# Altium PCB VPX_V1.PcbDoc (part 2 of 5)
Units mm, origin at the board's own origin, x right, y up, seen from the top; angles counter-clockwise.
Board outline 157.76 x 100.08 mm, 10 copper layers (Top Layer (PADS/SIG), Layer 2 (GND), Layer 3 (SIG), Layer 4 (SIG), Layer 5 (GND), Layer 6 (PWR), Layer 7 (GND), Layer 8 (SIG/PWR), Layer 9 (GND), Bottom Layer (PAD/SIG)), stack 1.614 mm thick; 383 components, 223 nets, 1313 pads, 1223 vias.
Unrouted connection lines stored in the file: 3.
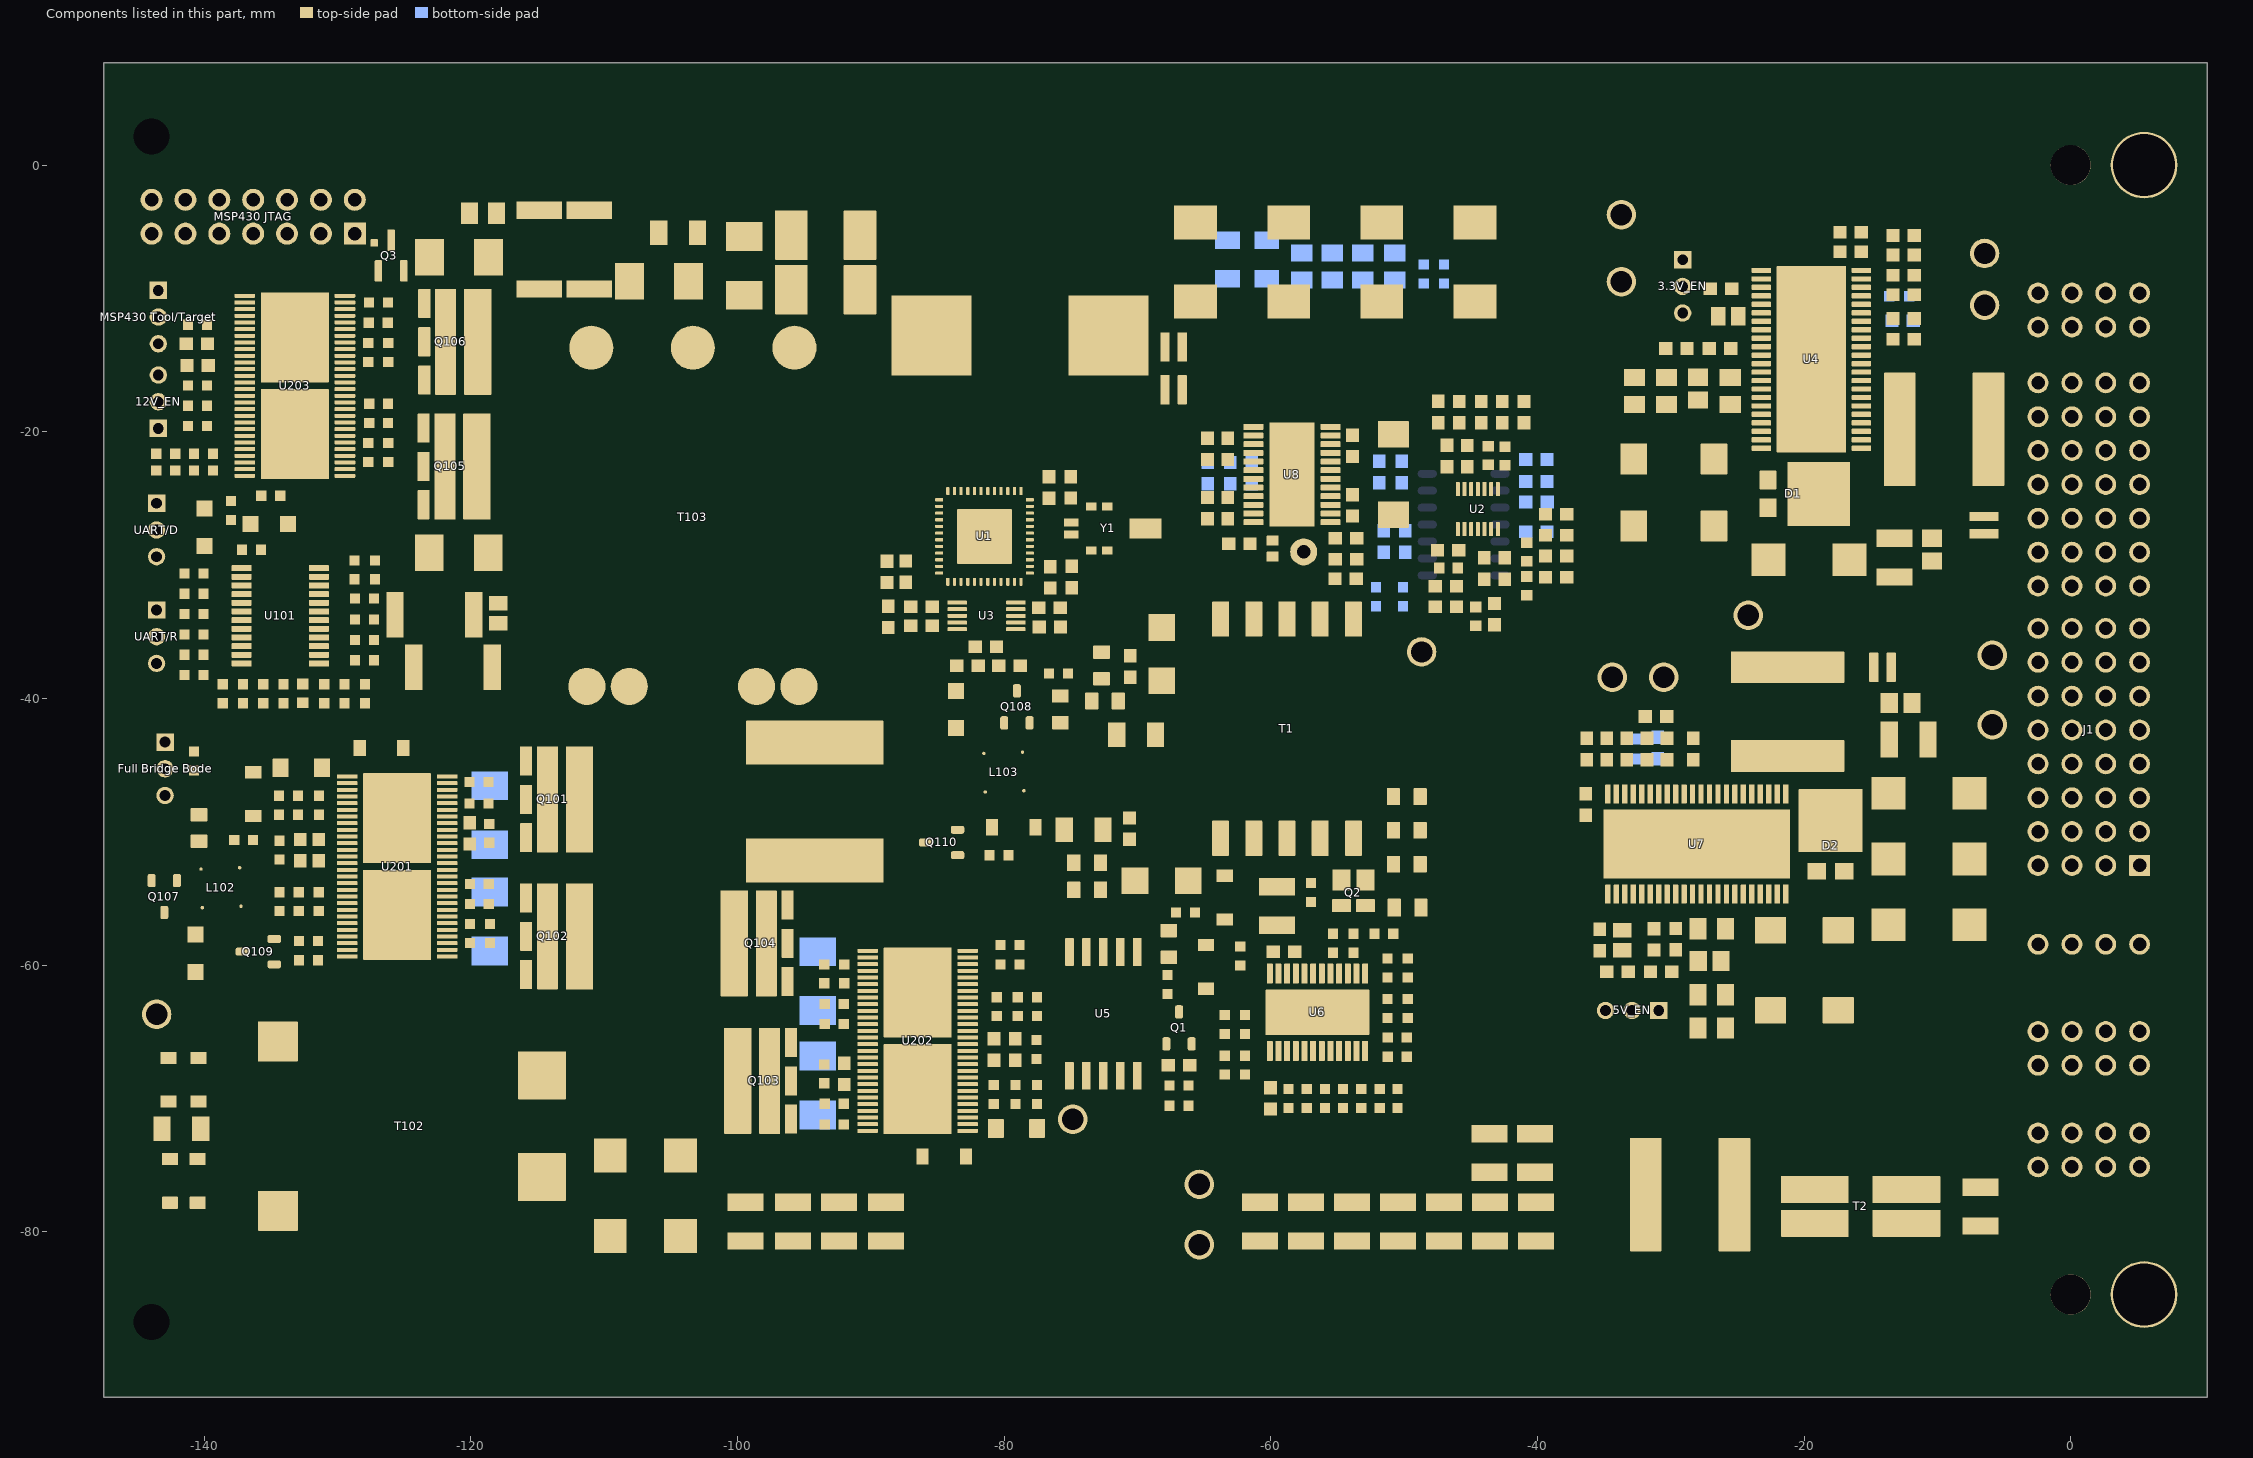
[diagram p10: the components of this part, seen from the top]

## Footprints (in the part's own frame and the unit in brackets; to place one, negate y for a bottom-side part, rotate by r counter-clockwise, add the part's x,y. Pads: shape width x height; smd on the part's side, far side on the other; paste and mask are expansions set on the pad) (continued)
DCA0056M-MFG [mm]
  rrect33% 1.55x0.3 smd paste+0 mask+0: 1(-3.75,6.75) 2(-3.75,6.25) 3(-3.75,5.75) 4(-3.75,5.25) 5(-3.75,4.75) 6(-3.75,4.25) 7(-3.75,3.75) 8(-3.75,3.25) 9(-3.75,2.75) 10(-3.75,2.25) 11(-3.75,1.75) 12(-3.75,1.25) 13(-3.75,0.75) 14(-3.75,0.25) 15(-3.75,-0.25) 16(-3.75,-0.75) 17(-3.75,-1.25) 18(-3.75,-1.75) 19(-3.75,-2.25) 20(-3.75,-2.75) 21(-3.75,-3.25) 22(-3.75,-3.75) 23(-3.75,-4.25) 24(-3.75,-4.75) 25(-3.75,-5.25) 26(-3.75,-5.75) 27(-3.75,-6.25) 28(-3.75,-6.75) 29(3.75,-6.75) 30(3.75,-6.25) 31(3.75,-5.75) 32(3.75,-5.25) 33(3.75,-4.75) 34(3.75,-4.25) 35(3.75,-3.75) 36(3.75,-3.25) 37(3.75,-2.75) 38(3.75,-2.25) 39(3.75,-1.75) 40(3.75,-1.25) 41(3.75,-0.75) 42(3.75,-0.25) 43(3.75,0.25) 44(3.75,0.75) 45(3.75,1.25) 46(3.75,1.75) 47(3.75,2.25) 48(3.75,2.75) 49(3.75,3.25) 50(3.75,3.75) 51(3.75,4.25) 52(3.75,4.75) 53(3.75,5.25) 54(3.75,5.75) 55(3.75,6.25) 56(3.75,6.75)
  rrect2% 5.1x6.75 smd paste-1000 mask-1000: 57(0,3.625) 58(0,-3.625)
  silkscreen extent -3.1,-7.42 3.1,7.42, body extent -4.62,-7.15 4.62,7.15, height 0.25
DDW0044F-MFG [mm] "Recommended Land Pattern"
  rrect25% 1.45x0.4 smd paste+0 mask+0: 1(-3.75,6.667) 2(-3.75,6.032) 3(-3.75,5.397) 4(-3.75,4.763) 5(-3.75,4.127) 6(-3.75,3.492) 7(-3.75,2.857) 8(-3.75,2.222) 9(-3.75,1.587) 10(-3.75,0.953) 11(-3.75,0.318) 12(-3.75,-0.318) 13(-3.75,-0.953) 14(-3.75,-1.587) 15(-3.75,-2.222) 16(-3.75,-2.857) 17(-3.75,-3.492) 18(-3.75,-4.127) 19(-3.75,-4.763) 20(-3.75,-5.397) 21(-3.75,-6.032) 22(-3.75,-6.667) 23(3.75,-6.667) 24(3.75,-6.032) 25(3.75,-5.397) 26(3.75,-4.763) 27(3.75,-4.127) 28(3.75,-3.492) 29(3.75,-2.857) 30(3.75,-2.222) 31(3.75,-1.587) 32(3.75,-0.953) 33(3.75,-0.318) 34(3.75,0.318) 35(3.75,0.953) 36(3.75,1.587) 37(3.75,2.222) 38(3.75,2.857) 39(3.75,3.492) 40(3.75,4.127) 41(3.75,4.763) 42(3.75,5.397) 43(3.75,6.032) 44(3.75,6.667)
  rrect2% 5.2x14 smd paste-1000 mask-1000: 45(0,0)
  silkscreen extent -5.15,-7.37 3.1,7.37, body extent -4.57,-7.3 4.57,7.3, height 0.25
DGS0010A-MFG [mm]
  rrect33% 1.45x0.3 smd paste+0 mask+0: 1(-2.2,1) 2(-2.2,0.5) 3(-2.2,0) 4(-2.2,-0.5) 5(-2.2,-1) 6(2.2,-1) 7(2.2,-0.5) 8(2.2,0) 9(2.2,0.5) 10(2.2,1)
  silkscreen extent -1.05,-1.55 1.05,1.55, body extent -2.45,-1.5 2.45,1.5, height 1.1
DYY0014A-MFG [mm]
  rrect33% 1.05x0.3 smd paste+0 mask+0: 1(-1.5,1.5) 2(-1.5,1) 3(-1.5,0.5) 4(-1.5,0) 5(-1.5,-0.5) 6(-1.5,-1) 7(-1.5,-1.5) 8(1.5,-1.5) 9(1.5,-1) 10(1.5,-0.5) 11(1.5,0) 12(1.5,0.5) 13(1.5,1) 14(1.5,1.5)
  silkscreen extent -1.05,-2.15 1.05,2.15, body extent -1.63,-2.1 1.63,2.1, height 1.1
FCC_disclaimer [mm]
FP-1-2000713-2_HDR1-MFG [mm] "Recommended Land Pattern"
  round 5 hole 4.65 paste-2539.97 mask+0: 1(0,4.125)
  round 3 hole 3 unplated paste-2539.97 mask+0: ""(0,9.625)
  silkscreen extent -4.5,0.82 4.5,11.44, body extent -4.5,-11.37 4.5,11.38, height 9.63
FP-2N2222AUB_SMT3-IPC_A [mm]
  rrect18% 1.6x0.55 smd paste+0 mask+0: 1(-1.15,0.955) 2(-1.15,-0.955) 3(1.15,0)
  rrect18% 0.559x0.559 smd paste+0 mask+0: 4(0.945,1.263)
  silkscreen extent -2.62,-1.63 1.37,1.63, body extent -1.22,-1.54 1.22,1.54, height 1.8
FP-1212VS-111MED_SMT_IND_11MM5_12MM0-MFG [mm] "Recommended Land Pattern"
  rrect3% 3.3x10.34 smd paste+0 mask+0: 1(-4.42,-1.465) 2(4.42,-1.465)
  silkscreen extent -5.75,-6 5.75,6, body extent -6.17,-6.74 6.17,6.1, height 0.25
FP-2563_RUBBER_BUMPER-MFG [mm]
  silkscreen extent -6.6,-6.6 6.6,6.6, body extent -6.35,-6.35 6.35,6.35, height 6.9
FP-63554-R01_SMT_XFRMR_24MM0_20MM0-MFG [mm]
  rrect3% 3.6x3.6 smd paste+0 mask+0: 1(-9.75,3.81) 2(-9.75,-3.81)
  rrect3% 3x3 smd paste+0 mask+0: 3(10.05,-6.35) 4(10.05,6.35)
  silkscreen extent -12.73,-10 12,10, body extent -12.1,-10.1 12.1,10.1, height 0.25
FP-6450839-7_CONN_PWR_HDR_8-32-MFG [mil] "Recommended Land Pattern"
  rrect6% 61.65x61.65 hole 40 paste-99999 mask+0: A1(-400,140)
  round 61.65 hole 40 paste-99999 mask+0: A2(-300,140) A3(-200,140) A4(-100,140) A5(0,140) A6(100,140) A7(200,140) A8(300,140) B1(-400,240) B2(-300,240) B3(-200,240) B4(-100,240) B5(0,240) B6(100,240) B7(200,240) B8(300,240) C1(-400,340) C2(-300,340) C3(-200,340) C4(-100,340) C5(0,340) C6(100,340) C7(200,340) C8(300,340) D1(-400,440) D2(-300,440) D3(-200,440) D4(-100,440) D5(0,440) D6(100,440) D7(200,440) D8(300,440) LP1(-632.5,140) LP1(-632.5,240) LP1(-632.5,340) LP1(-632.5,440) LP2(1025,240) LP2(1025,340) LP2(1025,440) LP2(1025,140) P1(-1290,140) P1(-1290,240) P1(-1290,340) P1(-1290,440) P1(-1190,140) P1(-1190,240) P1(-1190,340) P1(-1190,440) P2(-990,140) P2(-990,240) P2(-990,340) P2(-990,440) P2(-890,140) P2(-890,240) P2(-890,340) P2(-890,440) P3(425,140) P3(425,240) P3(425,340) P3(425,440) P3(525,240) P3(525,340) P3(525,440) P3(525,140) P4(625,140) P4(625,240) P4(625,340) P4(625,440) P4(725,240) P4(725,340) P4(725,440) P4(725,140) P5(825,140) P5(825,240) P5(825,340) P5(825,440) P5(925,140) P5(925,240) P5(925,340) P5(925,440) P6(1190,140) P6(1190,240) P6(1190,340) P6(1190,440) P6(1290,140) P6(1290,240) P6(1290,340) P6(1290,440)
  silkscreen extent -1439,-33 1415,468, body extent -1410,-465 1410,465, height 495
FP-885012206091_0603-MFG [mm]
  rrect13% 0.8x0.8 smd paste+0 mask+0: 1(-0.75,0) 2(0.75,0)
  silkscreen extent -0.85,-0.77 0.85,0.77, body extent -0.8,-0.4 0.8,0.4, height 0.87
FP-BAT46GWJ_SOD-123-MFG [mm]
  rrect11% 0.91x1.22 smd paste-1000 mask+0: 1(-1.635,0) 2(1.635,0)
  silkscreen extent -0.81,-0.85 0.81,0.85, body extent -2.29,-1.05 2.29,1.05, height 0.25
FP-C0603C472J5RAC7867_0603-MFG [mm]
  rrect13% 0.75x0.9 smd paste+0 mask+0: 1(-0.6,0) 2(0.6,0)
  silkscreen extent -0.87,-0.82 0.87,0.82, body extent -1.2,-0.6 1.2,0.6, height 0.25
FP-CP-D1549-BZ_SMT_XFRMR_29MM46_26MM67-MFG [mm]
  round 2.79 smd paste+0 mask+0: 1(-12.7,7.95) 2(-12.7,4.77) 5(-12.7,-4.77) 6(-12.7,-7.95)
  round 3.3 smd paste+0 mask+0: 7(12.7,-7.62) 9(12.7,0) 11(12.7,7.62)
  silkscreen extent -15.45,-13.33 14.73,13.33, body extent -14.83,-13.43 14.83,13.43, height 0.25
FP-CP-D1551-BZ_SMT_XFRMR_17MM75_14MM0-MFG [mm]
  rrect8% 2.64x1.27 smd paste+0 mask+0: 1(-8.22,4.98) 2(-8.22,2.49) 3(-8.22,0) 4(-8.22,-2.49) 5(-8.22,-4.98) 6(8.22,-4.98) 7(8.22,-2.49) 8(8.22,0) 9(8.22,2.49) 10(8.22,4.98)
  silkscreen extent -10.2,-7 8.87,7, body extent -9.64,-7.1 9.64,7.1, height 0.25
FP-CRM2512-FX-1002ELF_2512-MFG [mm]
  rrect4% 2.45x3.7 smd paste+0 mask+0: 1(-2.575,0) 2(2.575,0)
  silkscreen extent -0.97,-1.65 0.97,1.65, body extent -3.9,-1.95 3.9,1.95, height 0.25
FP-CSR0805FKR250_0805-MFG [mm]
  rrect10% 1x1.35 smd paste+0 mask+0: 1(-1,0) 2(1,0)
  silkscreen extent -0.3,-0.7 0.3,0.7, body extent -1.6,-0.8 1.6,0.8, height 0.25
FP-EPC7003AC_FSMD-A-MFG [mm]
  rrect10% 0.965x1.422 smd paste+0 mask+0: 1(-1.118,0.901) 3(-1.118,-0.901)
  rrect7% 1.6x1.346 smd paste+0 mask+0: 2(0.8,0.901) 4(0.8,-0.901)
  silkscreen extent -2.34,-2.04 1.71,2.04, body extent -1.81,-1.81 1.81,1.81, height 0.25
FP-EPC7018GC_FSMD-G-MFG [mm]
  rrect11% 2.184x0.914 smd paste+0 mask+0: 1(2.87,2.286) 2(-2.87,2.286) 5(0,2.286)
  rrect5% 7.95x2.057 smd paste+0 mask+0: 3(0,-1.714)
  rrect6% 7.95x1.575 smd paste+0 mask+0: 4(0,0.686)
  silkscreen extent -4.08,-3.25 4.77,3.25, body extent -4.18,-2.96 4.18,2.96, height 0.25
FP-KRL2012E-M-R004-F-T5_2012-MFG [mm]
  rrect14% 0.7x2.2 smd paste+0 mask+0: 1(-0.65,0) 2(0.65,0)
  silkscreen extent -0.77,-1.53 0.67,1.53, body extent -1.1,-1.2 1.1,1.2, height 0.25
FP-KRL2012E-M-R015-F-T5_0508-MFG [mm]
  rrect14% 0.7x2.2 smd paste+0 mask+0: 1(-0.65,0) 2(0.65,0)
  silkscreen extent -0.72,-1.5 0.72,1.5, body extent -1.1,-1.2 1.1,1.2, height 0.25
FP-SS1H20LW_SOD-123W-MFG [mm]
  rrect8% 1.2x1.4 smd paste+0 mask+0: 1(-1.55,0) 2(1.55,0)
  silkscreen extent -2.83,-0.95 0.58,0.95, body extent -1.85,-0.9 1.85,0.9, height 1.02
FP-SS10P4-M3_86A_SMPC-MFG [mm]
  rrect8% 1.4x1.27 smd paste+0 mask+0: 1(1.04,-2.765) 2(-1.04,-2.765)
  rrect2% 4.8x4.72 smd paste+0 mask+0: 3(0,1.04)
  silkscreen extent -2.18,-3.08 2.17,-1.7, body extent -2.5,-3.5 2.5,3.5, height 0.25
FP-T510X476M035ATE055_2917-MFG [mm]
  rrect5% 1.99x2.33 smd paste+0 mask+0: 1(-3.01,0) 2(3.01,0)
  silkscreen extent -3.8,-2.3 4.9,2.3, body extent -4.13,-2.42 4.13,2.42, height 0.25
FP-T521D107M025ATE040_2917-MFG [mm]
  rrect5% 1.99x2.33 smd paste+0 mask+0: 1(-3.01,0) 2(3.01,0)
  silkscreen extent -3.8,-2.3 4.9,2.3, body extent -4.13,-2.42 4.13,2.42, height 0.25
FP-XGL1010-103MED_SMT_IND_10MM0_11MM3-MFG [mm]
  rrect4% 2.38x8.5 smd paste+0 mask+0: 1(-3.325,0) 2(3.325,0)
  silkscreen extent -5.88,-5.9 5.25,5.9, body extent -5.35,-6 5.35,6, height 0.25
FP-XGL1060-182MEC_SMT2_10MM0_11MM3-MFG [mm]
  rrect4% 2.38x8.5 smd paste+0 mask+0: 1(-3.325,0) 2(3.325,0)
  silkscreen extent -5.25,-5.9 5.25,5.9, body extent -5.35,-6 5.35,6, height 0.25
FP-XGL1060-472MEC_SMT_IND_10MM0_11MM3-MFG [mm]
  rrect4% 2.38x8.5 smd paste+0 mask+0: 1(-3.325,0) 2(3.325,0)
  silkscreen extent -5.25,-5.9 5.25,5.9, body extent -5.35,-6 5.35,6, height 0.25
IEC_Caution_Small [mm]
  silkscreen extent -2.72,-2.36 2.72,2.35
Keystone5002 [mil] "For Keystone 500x miniature loop terminals"
  round 80 hole 40: 1(0,0)
  silkscreen extent -52,-52 52,52, body extent -49,-49 49,49, height 182
Keystone5010 [mil] "Keystone Multipurpose loops"
  round 87 hole 63: 1(0,0)
  silkscreen extent -70,-70 70,70, body extent -63,-63 63,62, height 319
Keystone5011 [mil] "Keystone Multipurpose loops"
  round 87 hole 63: 1(0,0)
  silkscreen extent -70,-70 70,70, body extent -63,-63 63,62, height 319
Keystone5012 [mil] "Keystone Multipurpose loops"
  round 87 hole 63: 1(0,0)
  silkscreen extent -70,-70 70,70, body extent -63,-63 63,62, height 319
Laird_Z171R-10 [mm] "SMD, 4-Leads, Body 10.03x8.51mm, Pitch 2.54mm"
  rrect5% 5.08x2.03 smd: 1(-3.435,1.27) 2(-3.435,-1.27) 3(3.435,-1.27) 4(3.435,1.27)
  body extent -5.52,-4.32 5.52,4.32, height 10.49
LPD4012 [mil] "Coilcraft"
  round 10 smd: 1(-59,55) 2(-55,-59) 3(59,-55) 4(55,59)
  Top Layer (PADS/SIG) region: -89,-24 -89,-55 -55,-89 -24,-89 -24,-60 -60,-24
  Top Layer (PADS/SIG) region: 89,-24 89,-55 55,-89 24,-89 24,-60 60,-24
  Top Layer (PADS/SIG) region: 89,24 89,55 55,89 24,89 24,60 60,24
  Top Layer (PADS/SIG) region: -89,24 -89,55 -55,89 -24,89 -24,60 -60,24
  silkscreen extent -97,-97 97,97, body extent -80,-80 78,78, height 41
NAC0010A-IPC_B [mm]
  rrect15% 2.09x0.65 smd paste+0 mask+0: 1(-4.64,2.54) 2(-4.64,1.27) 3(-4.64,0) 4(-4.64,-1.27) 5(-4.64,-2.54) 6(4.64,-2.54) 7(4.64,-1.27) 8(4.64,0) 9(4.64,1.27) 10(4.64,2.54)
  silkscreen extent -6.37,-3.43 3.31,3.43, body extent -5.88,-3.63 5.88,3.63, height 0.25
PW0024A-MFG [mm]
  rrect22% 1.5x0.45 smd paste+0 mask+0: 1(-2.9,3.575) 2(-2.9,2.925) 3(-2.9,2.275) 4(-2.9,1.625) 5(-2.9,0.975) 6(-2.9,0.325) 7(-2.9,-0.325) 8(-2.9,-0.975) 9(-2.9,-1.625) 10(-2.9,-2.275) 11(-2.9,-2.925) 12(-2.9,-3.575) 13(2.9,-3.575) 14(2.9,-2.925) 15(2.9,-2.275) 16(2.9,-1.625) 17(2.9,-0.975) 18(2.9,-0.325) 19(2.9,0.325) 20(2.9,0.975) 21(2.9,1.625) 22(2.9,2.275) 23(2.9,2.925) 24(2.9,3.575)
  silkscreen extent -4.38,-3.95 1.78,3.95, body extent -3.75,-4.2 3.75,4.2, height 0.25
PWP0024R-MFG [mm]
  rrect22% 1.5x0.45 smd paste+0 mask+0: 1(-2.9,3.575) 2(-2.9,2.925) 3(-2.9,2.275) 4(-2.9,1.625) 5(-2.9,0.975) 6(-2.9,0.325) 7(-2.9,-0.325) 8(-2.9,-0.975) 9(-2.9,-1.625) 10(-2.9,-2.275) 11(-2.9,-2.925) 12(-2.9,-3.575) 13(2.9,-3.575) 14(2.9,-2.925) 15(2.9,-2.275) 16(2.9,-1.625) 17(2.9,-0.975) 18(2.9,-0.325) 19(2.9,0.325) 20(2.9,0.975) 21(2.9,1.625) 22(2.9,2.275) 23(2.9,2.925) 24(2.9,3.575)
  rrect3% 3.4x7.8 smd paste-1000 mask-1000: 25(0,0)
  silkscreen extent -4.07,-4.3 2.25,4.32, body extent -3.75,-4.2 3.75,4.2, height 0.25
RGZ0048B [mm] "QFN, 48-Leads, Body 7x7mm, Pitch 0.5mm, Thermal Pad 5.15x5.15mm, TI Recommended"
  rrect42% 0.6x0.24 smd: 1(-3.4,2.75) 2(-3.4,2.25) 3(-3.4,1.75) 4(-3.4,1.25) 5(-3.4,0.75) 6(-3.4,0.25) 7(-3.4,-0.25) 8(-3.4,-0.75) 9(-3.4,-1.25) 10(-3.4,-1.75) 11(-3.4,-2.25) 12(-3.4,-2.75) 25(3.4,-2.75) 26(3.4,-2.25) 27(3.4,-1.75) 28(3.4,-1.25) 29(3.4,-0.75) 30(3.4,-0.25) 31(3.4,0.25) 32(3.4,0.75) 33(3.4,1.25) 34(3.4,1.75) 35(3.4,2.25) 36(3.4,2.75)
  rrect42% 0.24x0.6 smd: 13(-2.75,-3.4) 14(-2.25,-3.4) 15(-1.75,-3.4) 16(-1.25,-3.4) 17(-0.75,-3.4) 18(-0.25,-3.4) 19(0.25,-3.4) 20(0.75,-3.4) 21(1.25,-3.4) 22(1.75,-3.4) 23(2.25,-3.4) 24(2.75,-3.4) 37(2.75,3.4) 38(2.25,3.4) 39(1.75,3.4) 40(1.25,3.4) 41(0.75,3.4) 42(0.25,3.4) 43(-0.25,3.4) 44(-0.75,3.4) 45(-1.25,3.4) 46(-1.75,3.4) 47(-2.25,3.4) 48(-2.75,3.4)
  rrect9% 1.17x1.17 on Top Paste: 49(-1.37,1.37) 49(-1.37,0) 49(-1.37,-1.37) 49(0,0) 49(0,-1.37) 49(0,1.37) 49(1.37,1.37) 49(1.37,0) 49(1.37,-1.37)
  rrect2% 4.1x4.1 smd paste-2.575: 49(0,0)
  silkscreen extent -3.73,-3.73 3.73,3.73, body extent -3.5,-3.5 3.5,3.5, height 1.01
Samtec_PTT-103-01-x-S [mm] "Header, 2mm, 3x1, TH"
  rect 1.3x1.3 hole 0.81: 1(-2,0)
  round 1.3 hole 0.81: 2(0,0) 3(2,0)
  silkscreen extent -2.81,-0.99 2.81,1.3, body extent -3,-0.99 3,0.99, height 4.7
SMA [mm] "Molded Diode, 2-Leads, Body 4.3x2.6mm, IPC Medium Density, based on OnSemi component dimensions and land pattern"
  rect 2x2 smd: 1(-2,0) 2(2,0)
  silkscreen extent -3.66,-1.57 2.79,1.57, body extent -2.6,-1.3 2.6,1.3, height 2.42
SMB [mm] "Molded Diode, 2-Leads, Body 5.4x3.6mm, IPC Medium Density, based on OnSemi component dimensions"
  rect 2.159x2.743 smd: 1(-2.21,0) 2(2.21,0)
  silkscreen extent -3.94,-2.08 3.18,2.08, body extent -2.7,-1.8 2.7,1.8, height 2.32
SOD-123 [mm] "On Semi recommended land pattern"
  rect 0.915x1.22 smd: 1(-1.637,0) 2(1.637,0)
  silkscreen extent -2.74,-1.17 2.03,1.17, body extent -1.93,-0.9 1.93,0.9, height 1.35
SOD-123W [mm] "NXP recommended land pattern"
  rect 1.2x1.2 smd paste-0.05: 1(-1.4,0) 2(1.4,0)
  silkscreen extent -2.64,-1.14 1.68,1.14, body extent -1.85,-0.95 1.85,0.95, height 1.1
SOT-23 [mm] "SOT23, 3-Leads, Body 2.9x1.3mm, Pitch 0.95mm, Lead Span 2.5mm, IPC Medium Density"
  rrect50% 1x0.6 smd: 1(-1.2,0.95) 2(-1.2,-0.95) 3(1.2,0)
  silkscreen extent -1.63,-1.5 0.7,1.5, body extent -1.16,-1.45 1.21,1.45, height 1
WE-HCB_1890 [mm] "WURTH ELEKTRONIK"
  rect 6x6 smd: 1(-6.65,0) 2(6.65,0)
  silkscreen extent -9.7,-9.4 9.7,9.4, body extent -9.65,-9.35 9.65,9.35, height 9.2
WEEE_Minimum [mm] "WEEElie bin"
  silkscreen extent -2.42,-4.38 2.52,2.65
XTAL_MS3V-T1R [mm] "Micro Crystal Switzerland recommended land pattern"
  rect 1.1x0.6 smd: 1(-2.775,0.45) 2(-2.775,-0.45)
  rect 2.4x1.5 smd: 3(2.775,0)
  silkscreen extent -1.9,-0.74 1.2,0.74, body extent -3.05,-0.74 3.65,0.74, height 1.42

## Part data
"3.3V Bode" "3.3V Comp" "5V Bode": library part CMP-0055149-2, "Test Point, Multipurpose, White, TH", Color=White, Manufacturer="Keystone Electronics", PartNumber=5012, Supplier Part Number 1=36-5012-ND
3.3V_EN 5V_EN 12V_EN "Full Bridge Bode" "MSP430 Tool/Target" UART/D UART/R: library part CMP-0055571-1, "Header, 2mm, 3x1, Gold, TH", Color=Black, Current_A=2.9A, Manufacturer=Samtec
3.3V_Out 5V LDOCAP: library part CMP-0055147-2, "Test Point, Multipurpose, Red, TH", Color=Red, Manufacturer="Keystone Electronics", PartNumber=5010, Supplier Part Number 1=36-5010-ND
12V 12Vp_EXT 12Vs_EXT VIN_28V: library part CMP-0055147-2, "Test Point, Multipurpose, Red, TH", Color=Red, Manufacturer="Keystone Electronics", Supplier Part Number 1=36-5010-ND
C1 C2 C6 C7 C8 C9 C10 C11 C12 C13: library part CMP-0009231-2, "CAP, CERM, 1 uF, 100 V, +/- 10%, X7R, 1210", Cap_Case=1210, Manufacturer=MuRata, Supplier Part Number 1=490-1857-1-ND, TempCo=X7R, Tolerance_%=10%, Value1=Unknown, Value2=100V, ValueDisplayed=1uF
C3 C88: library part CMP-0085536-1, "CAP, CERM, 0.1 µF, 16 V,+/- 10%, X7R, 0603", Cap_Case=0603, Manufacturer="Samsung Electro-Mechanics", TempCo=X7R, Tolerance_%=10%, Value2=16V, ValueDisplayed=0.1µF
C4 C37 C42 C43 C44 C49 C89 C97 C100 C201 C202 C204 C206 C207 C209 C211 C212: library part CMP-0006867-4, "CAP, CERM, 1 uF, 25 V, +/- 10%, X7R, 0603", Cap_Case=0603, Manufacturer=Kemet, Supplier Part Number 1=399-7376-1-ND, TempCo=X7R, Tolerance_%=10%, Value1=Unknown, Value2=25V, ValueDisplayed=1uF
C5: library part CMP-0006983-4, "CAP, CERM, 2200 pF, 50 V, +/- 10%, X7R, 0603", Cap_Case=0603, Manufacturer=Kemet, Supplier Part Number 1=399-5341-1-ND, TempCo=X7R, Tolerance_%=10%, Value1=Unknown, Value2=50V, ValueDisplayed=2200pF
C14 C16: library part CMP-0079539-1, "CAP, CERM, 10 pF, 16 V,+/- 10%, C0G, 0402", Cap_Case=0402, Manufacturer=Kemet, Supplier Part Number 1=399-11110-1-ND, TempCo=C0G, Tolerance_%=10%, Value2=16V, ValueDisplayed=10pF
C15 C25 C66 C67: library part CMP-0012657-3, "CAP, Tantalum Polymer, 330 uF, 10 V, +/- 20%, 0.006 ohm, 7343-43 SMD", Cap_Case=7343-43, Manufacturer=Kemet, Supplier Part Number 1=399-4134-1-ND, Tolerance_%=20%, Value1="0.006 ohm", Value2=10V, ValueDisplayed=330uF
C17 C18 C58 C59: library part CMP-0096378-1, "Cap Tant Polymer 100uF 25VDC D CASE 20% (7.3 X 4.3 X 2.8mm) SMD 7343-31 0.04 Ohm 105C T/R", Digikey Part Number=399-13128-1-ND, Leakage Current=250uA, Manufacturer=KEMET, Mouser Part Number=80-T521D107M25ATE40, Operating Temperature Range="-55°C to +125°C", Tolerance_%=20%, ValueDisplayed=100uF
C19 C20 C107 C108: library part CMP-0860266-1, "CAP, CERM, 10 µF, 50 V,+/- 10%, X8L, AEC-Q200 Grade 0, 1210", Cap_Case=1210, Manufacturer=MuRata, TempCo=X8L, Tolerance_%=10%, Value2=50V, ValueDisplayed=10µF
C21 C62: library part CMP-0008305-2, "CAP, CERM, 22 uF, 25 V, +/- 20%, X5R, 0805", Cap_Case=0805, Manufacturer=MuRata, Supplier Part Number 1=490-10749-1-ND, TempCo=X5R, Tolerance_%=20%, Value1=Unknown, Value2=25V, ValueDisplayed=22uF
C22 C45 C46 C50 C51 C63: library part CMP-0008378-2, "CAP, CERM, 10 uF, 25 V, +/- 10%, X7R, 0805", Cap_Case=0805, Manufacturer=MuRata, Supplier Part Number 1=81-GRM21BZ71E106KE5L, TempCo=X7R, Tolerance_%=10%, Value1=Unknown, Value2=25V, ValueDisplayed=10uF
C23 C29 C34 C64 C70 C75: library part CMP-0080611-1, "CAP, CERM, 1 µF, 50 V,+/- 10%, X7R, 0805", Cap_Case=0805, Manufacturer=Samsung, Supplier Part Number 1=1276-2928-1-ND, TempCo=X7R, Tolerance_%=10%, Value2=50V, ValueDisplayed=1µF
C24 C65: library part CMP-0007725-2, "CAP, CERM, 0.1 uF, 50 V, +/- 10%, X7R, AEC-Q200 Grade 0, 0805", Cap_Case=0805, Manufacturer=Kemet, Supplier Part Number 1=399-6928-1-ND, TempCo=X7R, Tolerance_%=10%, Value1=Unknown, Value2=50V, ValueDisplayed=0.1uF
C26 C28 C30 C31 C60 C98 C106 C126: library part CMP-0084679-1, "CAP, CERM, 0.1 µF, 25 V,+/- 10%, X7R, AEC-Q200 Grade 1, 0603", Cap_Case=0603, Manufacturer=MuRata, TempCo=X7R, Tolerance_%=10%, Value2=25V, ValueDisplayed=0.1µF
C27 C68: library part CMP-0083755-1, "CAP, CERM, 22 µF, 16 V,+/- 10%, X7R, AEC-Q200 Grade 1, 1210", Cap_Case=1210, Manufacturer="Samsung Electro-Mechanics", TempCo=X7R, Tolerance_%=10%, Value2=16V, ValueDisplayed=22µF
C32 C73: library part CMP-0007050-4, "CAP, CERM, 0.47 uF, 50 V, +/- 10%, X7R, 0603", Cap_Case=0603, Manufacturer=TDK, Supplier Part Number 1=445-5952-1-ND, TempCo=X7R, Tolerance_%=10%, Value1="0.010974 ohm", Value2=50V, ValueDisplayed=0.47uF
C33 C74: library part CMP-0120895-1, "0.022 µF ±10% 50V Ceramic Capacitor X7R 0603 (1608 Metric)", Digikey Part Number=732-8009-1-ND, Manufacturer="Wurth Electronics", Mouser Part Number=710-885012206091, Operating Temperature Range="-55°C to +125°C", TempCo=15%, Temperature Characteristic=X7R, Tolerance_%=10%, ValueDisplayed=22nF
C35 C76: library part CMP-0006789-4, "CAP, CERM, 47 pF, 50 V, +/- 5%, C0G/NP0, 0603", Cap_Case=0603, Manufacturer=AVX, Supplier Part Number 1=478-1171-1-ND, TempCo=C0G/NP0, Tolerance_%=5%, Value1="0.174 ohm", Value2=50V, ValueDisplayed=47pF
C36 C77: library part CMP-0750039-1, "CAP, CERM, 0.01 µF, 50 V,+/- 10%, X7R, 0603", Cap_Case=0603, Manufacturer="Wurth Elektronik", TempCo=X7R, Tolerance_%=10%, Value2=50V, ValueDisplayed=0.01µF
C38 C39 C40 C41: library part CMP-0008309-2, "CAP, CERM, 4.7 uF, 50 V, +/- 10%, X5R, 0805", Cap_Case=0805, Manufacturer=MuRata, Supplier Part Number 1=GRM21BR61H475KE51L-ND, TempCo=X5R, Tolerance_%=10%, Value1=Unknown, Value2=50V, ValueDisplayed=4.7uF
C47: library part CMP-0007272-4, "CAP, CERM, 470 pF, 100 V, +/- 5%, C0G/NP0, 0603", Cap_Case=0603, Manufacturer=MuRata, Supplier Part Number 1=490-1367-1-ND, TempCo=C0G/NP0, Tolerance_%=5%, Value1=Unknown, Value2=100V, ValueDisplayed=470pF
C48: library part CMP-0007196-4, "CAP, CERM, 22 pF, 50 V, +/- 5%, C0G/NP0, 0603", Cap_Case=0603, Manufacturer=MuRata, Supplier Part Number 1=490-1411-1-ND, TempCo=C0G/NP0, Tolerance_%=5%, Value1=Unknown, Value2=50V, ValueDisplayed=22pF
C52: library part CMP-0007403-4, "CAP, CERM, 0.01 uF, 25 V, +/- 10%, X7R, 0603", Cap_Case=0603, Manufacturer=MuRata, Supplier Part Number 1=490-1520-1-ND, TempCo=X7R, Tolerance_%=10%, Value1=Unknown, Value2=25V, ValueDisplayed=0.01uF
C53 C57: library part CMP-0007402-5, "CAP, CERM, 1000 pF, 25 V, +/- 10%, X7R, 0603", Cap_Case=0603, Manufacturer=MuRata, Supplier Part Number 1=GRM188R71E102KA01D-ND, TempCo=X7R, Tolerance_%=10%, Value1=Unknown, Value2=25V, ValueDisplayed=1000pF
C54 C109: library part CMP-0007138-4, "CAP, CERM, 0.47 uF, 16 V, +/- 10%, X7R, AEC-Q200 Grade 1, 0603", Cap_Case=0603, Manufacturer=MuRata, Supplier Part Number 1=490-4775-1-ND, TempCo=X7R, Tolerance_%=10%, Value1=Unknown, Value2=16V, ValueDisplayed=0.47uF
C55: library part CMP-0007411-4, "CAP, CERM, 0.15 uF, 25 V, +/- 10%, X7R, 0603", Cap_Case=0603, Manufacturer=MuRata, Supplier Part Number 1=490-3289-1-ND, TempCo=X7R, Tolerance_%=10%, Value1=Unknown, Value2=25V, ValueDisplayed=0.15uF
C56: library part CMP-0007464-4, "CAP, CERM, 820 pF, 50 V, +/- 10%, X7R, 0603", Cap_Case=0603, Manufacturer=MuRata, Supplier Part Number 1=490-1493-1-ND, TempCo=X7R, Tolerance_%=10%, Value1=Unknown, Value2=50V, ValueDisplayed=820pF
C61: library part CMP-0006812-4, "CAP, CERM, 100 pF, 10 V, +/- 10%, X7R, 0603", Cap_Case=0603, Manufacturer=AVX, Supplier Part Number 1=0603ZC101KAT2A-ND, TempCo=X7R, Tolerance_%=10%, Value1=Unknown, Value2=10V, ValueDisplayed=100pF
C90 C91 C92 C93 C94 C95: library part CMP-0083857-1, "CAP, CERM, 100 pF, 50 V,+/- 10%, X7R, 0603", Cap_Case=0603, Manufacturer="Samsung Electro-Mechanics", TempCo=X7R, Tolerance_%=10%, Value2=50V, ValueDisplayed=100pF
C96: library part CMP-0860569-1, "CAP, CERM, 10 µF, 25 V,+/- 10%, X5R, 0603", Cap_Case=0603, Manufacturer=MuRata, TempCo=X5R, Tolerance_%=10%, Value2=25V, ValueDisplayed=10µF
C99: library part CMP-0121724-1, "47 µF Molded Tantalum Capacitors 35 V 2917 (7343 Metric) 55mOhm", Digikey Part Number=399-10324-1-ND, Leakage Current=16.5uA, Manufacturer=Kemet, Mouser Part Number=80-T510X476M35ATE055, Operating Temperature Range="-55°C to +125°C", Tolerance_%=20%, ValueDisplayed=47uF
C101 C115 C116: library part CMP-0007405-5, "CAP, CERM, 1 uF, 25 V, +/- 10%, X7R, 0603", Cap_Case=0603, Manufacturer=MuRata, Supplier Part Number 1=490-5307-1-ND, TempCo=X7R, Tolerance_%=10%, Value1=Unknown, Value2=25V, ValueDisplayed=1uF
C102 C103: library part CMP-0011753-2, "CAP, TA, 22 uF, 50 V, +/- 10%, 0.5 ohm, SMD", Cap_Case=7343-43, Manufacturer=Kemet, Supplier Part Number 1=399-10275-1-ND, Tolerance_%=10%, Value1="0.5 ohm", Value2=50V, ValueDisplayed=22uF
C104 C205 C210 C213 C214: library part CMP-0007499-4, "CAP, CERM, 2.2 uF, 16 V, +/- 10%, X7R, 0603", Cap_Case=0603, Manufacturer=MuRata, Supplier Part Number 1=81-GRM188Z71C225KE3D, TempCo=X7R, Tolerance_%=10%, Value1=Unknown, Value2=16V, ValueDisplayed=2.2uF
C105: library part CMP-0007425-5, "CAP, CERM, 5600 pF, 25 V, +/- 10%, X7R, 0603", Cap_Case=0603, Manufacturer=MuRata, Supplier Part Number 1=GRM188R71E562KA01D-ND, TempCo=X7R, Tolerance_%=10%, Value1=Unknown, Value2=25V, ValueDisplayed=5600pF
C110: library part CMP-0084283-1, "CAP, CERM, 10 pF, 100 V,+/- 5%, C0G/NP0, AEC-Q200 Grade 1, 0603", Cap_Case=0603, Manufacturer=MuRata, TempCo=C0G/NP0, Tolerance_%=5%, Value2=100V, ValueDisplayed=10pF
C111: library part CMP-0007427-5, "CAP, CERM, 6800 pF, 25 V, +/- 10%, X7R, 0603", Cap_Case=0603, Manufacturer=MuRata, Supplier Part Number 1=81-GRM18R71E682KA01D, TempCo=X7R, Tolerance_%=10%, Value1=Unknown, Value2=25V, ValueDisplayed=6800pF
C112: library part CMP-0007179-4, "CAP, CERM, 120 pF, 50 V, +/- 5%, C0G/NP0, 0603", Cap_Case=0603, Manufacturer=MuRata, Supplier Part Number 1=490-1429-1-ND, TempCo=C0G/NP0, Tolerance_%=5%, Value1=Unknown, Value2=50V, ValueDisplayed=120pF
C113 C114 C305 C306: library part CMP-0007171-4, "CAP, CERM, 100 pF, 50 V, +/- 5%, C0G/NP0, 0603", Cap_Case=0603, Manufacturer=MuRata, Supplier Part Number 1=490-1427-1-ND, TempCo=C0G/NP0, Tolerance_%=5%, Value1=Unknown, Value2=50V, ValueDisplayed=100pF
C117 C118: library part CMP-0008098-2, "CAP, CERM, 1200 pF, 100 V, +/- 5%, C0G/NP0, 0805", Cap_Case=0805, Manufacturer=MuRata, Supplier Part Number 1=GRM2165C2A122JA01D-ND, TempCo=C0G/NP0, Tolerance_%=5%, Value1=Unknown, Value2=100V, ValueDisplayed=1200pF
C119 C120: library part CMP-0082252-1, "CAP, CERM, 10 µF, 25 V,+/- 20%, X7R, AEC-Q200 Grade 1, 1206", Cap_Case=1206, Manufacturer=MuRata, Supplier Part Number 1=490-6519-1-ND, TempCo=X7R, Tolerance_%=20%, Value2=25V, ValueDisplayed=10µF
C121 C123 C124 C125: library part CMP-0012041-2, "CAP, TA, 100 uF, 25 V, +/- 10%, 0.1 ohm, SMD", Cap_Case=V, Manufacturer=AVX, Supplier Part Number 1=478-3104-1-ND, Tolerance_%=10%, Value1="0.1 ohm", Value2=25V, ValueDisplayed=100uF
C122: library part CMP-0008881-2, "CAP, CERM, 0.1 uF, 100 V, +/- 10%, X7R, 1206", Cap_Case=1206, Manufacturer=MuRata, Supplier Part Number 1=490-3364-1-ND, TempCo=X7R, Tolerance_%=10%, Value1=Unknown, Value2=100V, ValueDisplayed=0.1uF
C127: library part CMP-0006723-4, "CAP, CERM, 1000 pF, 100 V, +/- 5%, X7R, 0603", Cap_Case=0603, Manufacturer=AVX, Supplier Part Number 1=478-3698-1-ND, TempCo=X7R, Tolerance_%=5%, Value1="0.276 ohm", Value2=100V, ValueDisplayed=1000pF
C128: library part CMP-0120173-1, "4700 pF ±5% 50V Ceramic Capacitor X7R 0603 (1608 Metric)", Digikey Part Number=399-C0603C472J5RAC7867CT-ND, Manufacturer=KEMET, Mouser Part Number=80-C0603C472J5R, Operating Temperature Range="-55°C to +125°C", TempCo=15%, Temperature Characteristic=X7R, Tolerance_%=5%, ValueDisplayed=4700pF
C129: library part CMP-0007509-4, "CAP, CERM, 0.47 uF, 50 V, +/- 10%, X7R, 0603", Cap_Case=0603, Manufacturer="Taiyo Yuden", Supplier Part Number 1=587-3170-1-ND, TempCo=X7R, Tolerance_%=10%, Value1=Unknown, Value2=50V, ValueDisplayed=0.47uF
C203 C208: library part CMP-0079602-1, "CAP, CERM, 0.1 µF, 50 V,+/- 10%, X7R, AEC-Q200 Grade 1, 0603", Cap_Case=0603, Manufacturer=Kemet, Supplier Part Number 1=399-6856-1-ND, TempCo=X7R, Tolerance_%=10%, Value2=50V, ValueDisplayed=0.1µF
C301 C302 C303 C304: library part CMP-0008346-3, "CAP, CERM, 4.7 uF, 25 V, +/- 10%, X7R, 0805", Cap_Case=0805, Manufacturer=MuRata, Supplier Part Number 1=490-9962-1-ND, TempCo=X7R, Tolerance_%=10%, Value1=Unknown, Value2=25V, ValueDisplayed=4.7uF
D1 D2: library part CMP-0120824-2, "Diode 40 V 10A Surface Mount TO-277A (SMPC)", Digikey Part Number=SS10P4-M3/86AGICT-ND, Forward Current=10A, Manufacturer=Vishay, Max Surge Forward Current=280A, Mouser Part Number=625-SS10P4-M3, Operating Temperature Range="-55°C to +150°C", Peak Reverse Current=100uA, ValueDisplayed=750pF
D3 D4 D9 D10 D106 D107 D109 D110: library part CMP-0028521-2, "Diode, Schottky, 100 V, 1 A, SMB", Manufacturer="ON Semiconductor", Value1=1A, Value2=0.75V
D5 D8: library part CMP-0028361-2, "Diode, Schottky, 60 V, 0.015 A, SOD-123", Manufacturer="Diodes Inc.", Value1=0.015A, Value2=0.8V
D6 D7: library part CMP-0028585-2, "Diode, Schottky, 60 V, 1 A, SMA", Manufacturer="ON Semiconductor", Value1=1A, Value2=0.72V
D101 D102 D103 D104: library part CMP-0090343-1, "Diode Schottky 100V 250mA (DC) Surface Mount SOD-123", Digikey Part Number=1727-7326-1-ND, Forward Current=250mA, Manufacturer=Nexperia, Max Surge Forward Current=2.5A, Mouser Part Number=841-BAT46GWJ, Operating Temperature Range="to +150°C", Peak Reverse Current=2uA, ValueDisplayed=39pF
D105 D108 D111 D112: library part CMP-0080763-2, "Diode, Schottky, 40 V, 3 A, AEC-Q101, SOD-123W", Manufacturer=Nexperia, Value1=3A, Value2=0.54V
D113 D114: library part CMP-0076974-2, "Diode, Switching, 100 V, 0.15 A, SOD-123", Manufacturer="Micro Commercial Components", Value1=0.15A, Value2=1.25V
D201 D203: library part CMP-0095320-1, "Diode Schottky 200 V 1A Surface Mount SOD-123W", Digikey Part Number=SS1H20LWRVGCT-ND, Forward Current=1A, Manufacturer="Taiwan Semiconductor", Max Surge Forward Current=30A, Mouser Part Number=821-SS1H20LW, Operating Temperature Range="-55°C to +175°C", Peak Reverse Current=0.1mA
D202 D204: library part CMP-0005752-4, "Diode, Zener, 13 V, 500 mW, SOD-123", Manufacturer="Diodes Inc.", Power_W=500mW, Value1=0.5W
J1: library part CMP-0127211-1, "Conn Power HDR 8Power/32Signal POS 2.54mm/5.08mm Solder RA Thru-Hole 88 Terminal 1 Port", Current_A=50A, Digikey Part Number=6450839-7-ND, Manufacturer="TE Connectivity", Mouser Part Number=571-6450839-7, Operating Temperature Range="-40°C to +125°C", Voltage_V=300V
J2 J4: library part CMP-0127380-1, "Connector Guide Module For MULTIGIG RT 2-R Series", Digikey Part Number=A132120-ND, Manufacturer="TE Connectivity", Mouser Part Number=571-1-2000713-2, Operating Temperature Range="-55°C to +125°C"
L1: library part CMP-0121657-1, "4.7 µH Shielded Molded Inductor 18.2 A 8.5mOhm Max Nonstandard", Digikey Part Number=2457-XGL1060-472MEC-ND, Manufacturer=Coilcraft, Operating Temperature Range=to, Self Resonant Frequency=18MHz, Test Frequency=1MHz, Tolerance_%=20%
L2: library part CMP-0001536-1, "Shielded Power Inductors 1.8uH 28.2A 3.2mOhms AEC-Q200 Grade 1", Manufacturer=Coilcraft, Operating Temperature Range=to, Self Resonant Frequency=28MHz, Test Frequency=1MHz, Tolerance_%=20%
L3: library part CMP-0120510-1, "10 µH Shielded Molded Inductor 18.2 A 9.7mOhm Max Nonstandard", Digikey Part Number=2457-XGL1010-103MED-ND, Manufacturer=Coilcraft, Operating Temperature Range=to, Self Resonant Frequency=12MHz, Test Frequency=1MHz, Tolerance_%=20%
L101: library part CMP-0064040-1, "Inductor, Shielded Drum Core, WE-Superflux200, 1.3 uH, 34.5 A, 0.0009 ohm, SMD", Manufacturer="Wurth Elektronik", Supplier Part Number 1=732-2168-1-ND, Value1="0.0009 ohm", Value2=34.5A, ValueDisplayed=1.3uH
L102 L103: library part CMP-0012812-2, "Coupled inductor, 22 uH, 0.7 A, 1.63 ohm, TH", Manufacturer=Coilcraft, Supplier Part Number 1=994-LPD4012-333MRB, ValueDisplayed=22uH
L301: library part CMP-0125020-1, "Air Core Inductor, High Current, 117 nH, 44 A, 1212VS Series, ± 20%, 0.00143 ohm, 399 MHz", Manufacturer=Coilcraft, Mouser Part Number=994-1212VS-111MED, Operating Temperature Range=to, Self Resonant Frequency=399MHz, Test Frequency=1MHz, Tolerance_%=20%
LDO_BODE: library part CMP-0055139-2, "Test Point, Miniature, White, TH", Color=White, Manufacturer="Keystone Electronics", PartNumber=5002, Supplier Part Number 1=36-5002-ND
Logo1: library part CMP-0074769-1
Logo2: library part CMP-0074847-1, "FCC_disclaimer"
Logo3: library part CMP-0074836-1, "IEC 61010-1 Caution Warning"
MP1 MP2 MP3 MP4: library part CMP-0091591-1, "Bumper / Feet, Stick On, Pack, Adhesive, 6.4 mm, 12.7 mm, Round, Transparent", Manufacturer=Multicomp, Operating Temperature Range=to
"MSP430 JTAG": library part CMP-0054695-2, "Header (shrouded), 100 mil, 7x2, Gold, TH", Manufacturer="Sullins Connector Solutions", Supplier Part Number 1=S9170-ND
PGND_1 SGND_1: library part CMP-0055148-2, "Test Point, Multipurpose, Black, TH", Color=Black, Manufacturer="Keystone Electronics", Supplier Part Number 1=36-5011-ND
Q1: library part CMP-0000511-2, "Transistor, NPN, 50 V, 0.1 A, AEC-Q101, SOT-23", Manufacturer="ON Semiconductor", Supplier Part Number 1=MMUN2214LT1GOSCT-ND, Value1="0.1 A"
Q2: library part CMP-0041262-1, "N-Channel 100 V 10A (Tc) Surface Mount 4-SMD", Digikey Part Number=4107-EPC7003AC-ND, Drain To Source Breakdown Voltage=100V, Input Capacitace At Vds="168pF @ 50V", Manufacturer="EPC Space", Operating Temperature Range="-55°C to +150°C", Pulse Drain Current=42A, Typ Forward Diode Voltage=1.7V
Q3: library part CMP-0098458-1, "Bipolar (BJT) Transistor NPN 50 V 800 mA 500 mW Surface Mount 3-SMD", Collector Base Voltage=75V, Digikey Part Number=2N2222AUBMS-ND, Emitter Base Voltage=6V, Manufacturer=Microchip, Mouser Part Number=494-2N2222AUB, Operating Temperature Range="-65°C to +200°C", Power_W=0.5W
Q101 Q102 Q103 Q104 Q105 Q106: library part CMP-0047628-1, "MOSFET N-Channel 100 V 80A (Tc) Surface Mount 5-SMD", Digikey Part Number=4107-EPC7018GC-ND, Drain To Source Breakdown Voltage=100V, Input Capacitace At Vds="1240pF @ 50V", Manufacturer="EPC Space", Operating Temperature Range="-55°C to +150°C", Pulse Drain Current=345A
Q107 Q108: library part CMP-0000755-1, "MOSFET, N-CH, 50 V, 0.22 A, SOT-23", Alternate Manufacturer=None, Manufacturer="Fairchild Semiconductor", Supplier Part Number 1=BSS138CT-ND, Value2="1.7 nC"
Q109 Q110: library part CMP-0000331-2, "Transistor, PNP, 60 V, 0.8 A, SOT-23", Manufacturer="Fairchild Semiconductor", Supplier Part Number 1=MMBT2907AFSCT-ND, Value1="0.8 A", Value2=300
R1 R2 R32: library part CMP-0095678-1, "4 mOhms ±1% 1W Chip Resistor Wide 0805 (2012 Metric), 0508 Automotive AEC-Q200, Current Sense Metal Foil", Digikey Part Number=408-1594-1-ND, Manufacturer=Susumu, Mouser Part Number=754-KRL2012EMR004FT5, Operating Temperature Range="-55°C to +155°C", Power_W=1W, TempCo=50ppm/°C, Tolerance_%=1%
R3: library part CMP-0097245-1, "15 mOhms ±1% 1W Chip Resistor Wide 0805 (2012 Metric), 0508 Automotive AEC-Q200, Current Sense Metal Foil", Digikey Part Number=408-1601-1-ND, Manufacturer=Susumu, Mouser Part Number=754-KRL2012EMR015FT5, Operating Temperature Range="-55°C to +155°C", Power_W=1W, TempCo=50ppm/°C, Tolerance_%=1%
R4 R5 R8 R9 R12 R14: library part CMP-0022779-5, "RES, 12.0 k, 1%, 0.1 W, 0603", Manufacturer=Yageo, Power_W=100mW, Supplier Part Number 1=311-12.0KHRCT-ND, TempCo="100 ppm/C", Tolerance_%=1%, Value2=0.1W, Value_Code=12k0, ValueDisplayed=12.0k
R6 R10: library part CMP-0022579-4, "RES, 715 k, 1%, 0.1 W, AEC-Q200 Grade 0, 0603", Manufacturer=Vishay-Dale, Power_W=100mW, Supplier Part Number 1=541-715KHCT-ND, TempCo="100 ppm/C", Tolerance_%=1%, Value2=0.1W, Value_Code=715k
R7 R11: library part CMP-0022587-4, "RES, 750 k, 1%, 0.1 W, AEC-Q200 Grade 0, 0603", Manufacturer=Vishay-Dale, Power_W=100mW, Supplier Part Number 1=541-750KHCT-ND, TempCo="100 ppm/C", Tolerance_%=1%, Value2=0.1W, Value_Code=750k
R13 R15: library part CMP-0022614-3, "RES, 806 k, 1%, 0.1 W, AEC-Q200 Grade 0, 0603", Manufacturer=Vishay-Dale, Power_W=100mW, Supplier Part Number 1=541-806KHCT-ND, TempCo="100 ppm/C", Tolerance_%=1%, Value2=0.1W, Value_Code=806k
R16 R17: library part CMP-0022895-5, "RES, 1.00 k, 1%, 0.1 W, 0603", Manufacturer=Yageo, Power_W=100mW, Supplier Part Number 1=311-1.00KHRCT-ND, TempCo="100 ppm/C", Tolerance_%=1%, Value2=0.1W, Value_Code=1k00, ValueDisplayed=1.00k
R18 R19 R20 R21: library part CMP-0023198-5, "RES, 5.10 k, 1%, 0.1 W, 0603", Manufacturer=Yageo, Power_W=100mW, Supplier Part Number 1=311-5.10KHRCT-ND, TempCo="100 ppm/C", Tolerance_%=1%, Value2=0.1W, Value_Code=5k10, ValueDisplayed=5.10k
R22: library part CMP-0022746-5, "RES, 10.0 k, 1%, 0.1 W, 0603", Manufacturer=Yageo, Power_W=100mW, Supplier Part Number 1=311-10.0KHRCT-ND, TempCo="100 ppm/C", Tolerance_%=1%, Value2=0.1W, Value_Code=10k0, ValueDisplayed=10.0k
R23: library part CMP-0022705-3, "RES, 49.9 k, 1%, 0.1 W, AEC-Q200 Grade 0, 0603", Manufacturer=Panasonic, Power_W=100mW, Supplier Part Number 1=P49.9KHCT-ND, TempCo="100 ppm/C", Tolerance_%=1%, Value2=0.1W, Value_Code=49k9, ValueDisplayed=49.9k
R24: library part CMP-0023133-5, "RES, 47.0 k, 1%, 0.1 W, 0603", Manufacturer=Yageo, Power_W=100mW, Supplier Part Number 1=311-47.0KHRCT-ND, TempCo="100 ppm/C", Tolerance_%=1%, Value2=0.1W, Value_Code=47k0, ValueDisplayed=47.0k
R25 R26 R30 R50 R56 R80 R122 R123 R206 R212 R213 R219 R225 R226 R228 R235 R236: library part CMP-0021998-4, "RES, 10.0 k, 1%, 0.1 W, AEC-Q200 Grade 0, 0603", Manufacturer=Vishay-Dale, Power_W=100mW, Supplier Part Number 1=541-10.0KHCT-ND, TempCo="100 ppm/C", Tolerance_%=1%, Value2=0.1W, Value_Code=10k0, ValueDisplayed=10.0k
R27: library part CMP-0023098-5, "RES, 40.2 k, 1%, 0.1 W, 0603", Manufacturer=Yageo, Power_W=100mW, Supplier Part Number 1=311-40.2KHRCT-ND, TempCo="100 ppm/C", Tolerance_%=1%, Value2=0.1W, Value_Code=40k2, ValueDisplayed=40.2k
R28 R57: library part CMP-0022109-5, "RES, 1.00 k, 1%, 0.1 W, AEC-Q200 Grade 0, 0603", Manufacturer=Vishay-Dale, Power_W=100mW, Supplier Part Number 1=541-1.00KHCT-ND, TempCo="100 ppm/C", Tolerance_%=1%, Value2=0.1W, Value_Code=1k00, ValueDisplayed=1.00k
R29: library part CMP-0022336-4, "RES, 332 k, 1%, 0.1 W, AEC-Q200 Grade 0, 0603", Manufacturer=Vishay-Dale, Power_W=100mW, Supplier Part Number 1=541-332KHCT-ND, TempCo="100 ppm/C", Tolerance_%=1%, Value2=0.1W, Value_Code=332k
R31 R37 R67: library part CMP-0023387-3, "RES, 50, 0.1%, 0.125 W, 0603", Manufacturer="Vishay Thin Film", Power_W=125mW, Supplier Part Number 1=FC0603-50BFCT-ND, TempCo="25 ppm/C", Tolerance_%=0.1%, Value2=0.125W, Value_Code=50R0, ValueDisplayed=50
R33 R36: library part CMP-0025401-2, "RES, 54.2 k, 0.5%, 0.1 W, 0603", Manufacturer="Yageo America", Power_W=100mW, TempCo="50 ppm/C", Tolerance_%=0.5%, Value2=0.1W, Value_Code=54k2, ValueDisplayed=54.2k
R34 R35 R38 R39 R41 R68 R69 R79: library part CMP-0023653-3, "RES, 10.0 k, 0.1%, 0.1 W, 0603", Manufacturer="Yageo America", Power_W=100mW, TempCo="25 ppm/C", Tolerance_%=0.1%, Value2=0.1W, Value_Code=10k0, ValueDisplayed=10.0k
R40: library part CMP-0022984-5, "RES, 2.21 k, 1%, 0.1 W, 0603", Manufacturer=Yageo, Power_W=100mW, Supplier Part Number 1=311-2.21KHRCT-ND, TempCo="100 ppm/C", Tolerance_%=1%, Value2=0.1W, Value_Code=2k21, ValueDisplayed=2.21k
R42 R72: library part CMP-0024528-3, "RES, 90.9 k, 0.1%, 0.1 W, 0603", Manufacturer="Yageo America", Power_W=100mW, TempCo="25 ppm/C", Tolerance_%=0.1%, Value2=0.1W, Value_Code=90k9, ValueDisplayed=90.9k
R43: library part CMP-0024020-3, "RES, 271 k, 0.1%, 0.1 W, 0603", Manufacturer="Yageo America", Power_W=100mW, TempCo="25 ppm/C", Tolerance_%=0.1%, Value2=0.1W, Value_Code=271k
R44: library part CMP-0024230-3, "RES, 42.2 k, 0.1%, 0.1 W, 0603", Manufacturer="Yageo America", Power_W=100mW, TempCo="25 ppm/C", Tolerance_%=0.1%, Value2=0.1W, Value_Code=42k2, ValueDisplayed=42.2k
R45: library part CMP-0024309-3, "RES, 511 k, 0.1%, 0.1 W, 0603", Manufacturer="Yageo America", Power_W=100mW, TempCo="25 ppm/C", Tolerance_%=0.1%, Value2=0.1W, Value_Code=511k
R46 R65 R76 R104 R230: library part CMP-0022447-4, "RES, 49.9 k, 1%, 0.1 W, AEC-Q200 Grade 0, 0603", Manufacturer=Vishay-Dale, Power_W=100mW, Supplier Part Number 1=541-49.9KHCT-ND, TempCo="100 ppm/C", Tolerance_%=1%, Value2=0.1W, Value_Code=49k9, ValueDisplayed=49.9k
R47 R102: library part CMP-0022589-4, "RES, 75.0 k, 1%, 0.1 W, AEC-Q200 Grade 0, 0603", Manufacturer=Vishay-Dale, Power_W=100mW, Supplier Part Number 1=541-75.0KHCT-ND, TempCo="100 ppm/C", Tolerance_%=1%, Value2=0.1W, Value_Code=75k0, ValueDisplayed=75.0k
R48: library part CMP-0022237-4, "RES, 24.9 k, 1%, 0.1 W, AEC-Q200 Grade 0, 0603", Manufacturer=Vishay-Dale, Power_W=100mW, Supplier Part Number 1=541-24.9KHCT-ND, TempCo="100 ppm/C", Tolerance_%=1%, Value2=0.1W, Value_Code=24k9, ValueDisplayed=24.9k
R49 R203 R205 R215 R218: library part CMP-0021990-4, "RES, 100 k, 1%, 0.1 W, AEC-Q200 Grade 0, 0603", Manufacturer=Vishay-Dale, Power_W=100mW, Supplier Part Number 1=541-100KHCT-ND, TempCo="100 ppm/C", Tolerance_%=1%, Value2=0.1W, Value_Code=100k
R51 R55: library part CMP-0022396-4, "RES, 3.01, 1%, 0.1 W, AEC-Q200 Grade 0, 0603", Manufacturer=Vishay-Dale, Power_W=100mW, Supplier Part Number 1=541-3.01HHCT-ND, TempCo="100 ppm/C", Tolerance_%=1%, Value2=0.1W, Value_Code=3R01, ValueDisplayed=3.01
R52: library part CMP-0022283-4, "RES, 2.87 k, 1%, 0.1 W, AEC-Q200 Grade 0, 0603", Manufacturer=Vishay-Dale, Power_W=100mW, Supplier Part Number 1=541-2.87KHCT-ND, TempCo="100 ppm/C", Tolerance_%=1%, Value2=0.1W, Value_Code=2k87, ValueDisplayed=2.87k
R53: library part CMP-0022374-4, "RES, 3.24 k, 1%, 0.1 W, AEC-Q200 Grade 0, 0603", Manufacturer=Vishay-Dale, Power_W=100mW, Supplier Part Number 1=541-3.24KHCT-ND, TempCo="100 ppm/C", Tolerance_%=1%, Value2=0.1W, Value_Code=3k24, ValueDisplayed=3.24k
R54: library part CMP-0018603-3, "RES, 1.0 k, 5%, 0.25 W, AEC-Q200 Grade 0, 1206", Manufacturer=Vishay-Dale, Power_W=250mW, Supplier Part Number 1=541-1.0KECT-ND, TempCo="200 ppm/C", Tolerance_%=5%, Value2=0.25W, Value_Code=1k00, ValueDisplayed=1.0k
R58: library part CMP-0088568-2, "250 mOhms ±1% 0.25W, 1/4W Chip Resistor 0805 (2012 Metric) Current Sense Thick Film", Digikey Part Number=CSR0805FKR250CT-ND, Manufacturer="Stackpole Electronics Inc", Operating Temperature Range="-55°C to +155°C", Power_W=250mW, TempCo=200ppm/°C, Tolerance_%=1%, ValueDisplayed=0.25
R59: library part CMP-0083479-1, "RES, 1.0 k, 5%, 0.5 W, 1210", Manufacturer=Yageo, Power_W=500mW, TempCo="100 ppm/C", Tolerance_%=5%, Value2=0.5W, Value_Code=1k00, ValueDisplayed=1.0k
R60: library part CMP-0018641-3, "RES, 2.2 k, 5%, 0.25 W, AEC-Q200 Grade 0, 1206", Manufacturer=Vishay-Dale, Power_W=250mW, Supplier Part Number 1=541-2.2KECT-ND, TempCo="200 ppm/C", Tolerance_%=5%, Value2=0.25W, Value_Code=2k20, ValueDisplayed=2.2k
R61: library part CMP-0022603-4, "RES, 7.87 k, 1%, 0.1 W, AEC-Q200 Grade 0, 0603", Manufacturer=Vishay-Dale, Power_W=100mW, Supplier Part Number 1=541-7.87KHCT-ND, TempCo="100 ppm/C", Tolerance_%=1%, Value2=0.1W, Value_Code=7k87, ValueDisplayed=7.87k
R62: library part CMP-0022014-4, "RES, 118 k, 1%, 0.1 W, AEC-Q200 Grade 0, 0603", Manufacturer=Vishay-Dale, Power_W=100mW, Supplier Part Number 1=541-118KHCT-ND, TempCo="100 ppm/C", Tolerance_%=1%, Value2=0.1W, Value_Code=118k
R63: library part CMP-0022445-4, "RES, 499 k, 1%, 0.1 W, AEC-Q200 Grade 0, 0603", Manufacturer=Vishay-Dale, Power_W=100mW, Supplier Part Number 1=541-499KHCT-ND, TempCo="100 ppm/C", Tolerance_%=1%, Value2=0.1W, Value_Code=499k
R64: library part CMP-0022202-4, "RES, 205 k, 1%, 0.1 W, AEC-Q200 Grade 0, 0603", Manufacturer=Vishay-Dale, Power_W=100mW, Supplier Part Number 1=541-205KHCT-ND, TempCo="100 ppm/C", Tolerance_%=1%, Value2=0.1W, Value_Code=205k
R66 R126: library part CMP-0022559-4, "RES, 6.19 k, 1%, 0.1 W, AEC-Q200 Grade 0, 0603", Manufacturer=Vishay-Dale, Power_W=100mW, Supplier Part Number 1=541-6.19KHCT-ND, TempCo="100 ppm/C", Tolerance_%=1%, Value2=0.1W, Value_Code=6k19, ValueDisplayed=6.19k
R70: library part CMP-0022876-5, "RES, 1.37 k, 1%, 0.1 W, 0603", Manufacturer=Yageo, Power_W=100mW, Supplier Part Number 1=311-1.37KHRCT-ND, TempCo="100 ppm/C", Tolerance_%=1%, Value2=0.1W, Value_Code=1k37, ValueDisplayed=1.37k
R71: library part CMP-0022703-3, "RES, 4.53 k, 1%, 0.1 W, AEC-Q200 Grade 0, 0603", Manufacturer=Panasonic, Power_W=100mW, Supplier Part Number 1=P4.53KHCT-ND, TempCo="100 ppm/C", Tolerance_%=1%, Value2=0.1W, Value_Code=4k53, ValueDisplayed=4.53k
R73: library part CMP-0023464-3, "RES, 20.0 k, 0.1%, 0.1 W, 0603", Manufacturer="Susumu Co Ltd", Power_W=100mW, Supplier Part Number 1=RG16P20.0KBCT-ND, TempCo="25 ppm/C", Tolerance_%=0.1%, Value2=0.1W, Value_Code=20k0, ValueDisplayed=20.0k
R74: library part CMP-0024410-2, "RES, 65.7 k, 0.1%, 0.1 W, 0603", Manufacturer="Yageo America", Power_W=100mW, TempCo="25 ppm/C", Tolerance_%=0.1%, Value2=0.1W, Value_Code=65k7, ValueDisplayed=65.7k
R75: library part CMP-0025808-4, "RES, 430 k, 5%, 0.1 W, AEC-Q200 Grade 0, 0603", Manufacturer=Vishay-Dale, Power_W=100mW, Supplier Part Number 1=541-430KGCT-ND, TempCo="200 ppm/C", Tolerance_%=5%, Value2=0.1W, Value_Code=430k
R77 R78 R81 R82 R107 R109 R201 R202 R214 R216 R227 R229 R237 R238: library part CMP-0025697-4, "RES, 0, 5%, 0.1 W, AEC-Q200 Grade 0, 0603", Manufacturer=Vishay-Dale, Power_W=100mW, Supplier Part Number 1=541-0.0GCT-ND, TempCo="200 ppm/C", Tolerance_%=5%, Value2=0.1W, Value_Code=0000, ValueDisplayed=0
R83 R84: library part CMP-0022769-5, "RES, 120, 1%, 0.1 W, 0603", Manufacturer=Yageo, Power_W=100mW, Supplier Part Number 1=311-120HRCT-ND, TempCo="100 ppm/C", Tolerance_%=1%, Value2=0.1W, Value_Code=120R, ValueDisplayed=120
R101: library part CMP-0022052-4, "RES, 147 k, 1%, 0.1 W, AEC-Q200 Grade 0, 0603", Manufacturer=Vishay-Dale, Power_W=100mW, Supplier Part Number 1=541-147KHCT-ND, TempCo="100 ppm/C", Tolerance_%=1%, Value2=0.1W, Value_Code=147k
R103: library part CMP-0016768-3, "RES, 1.69, 1%, 0.25 W, AEC-Q200 Grade 0, 1206", Manufacturer=Vishay-Dale, Power_W=250mW, Supplier Part Number 1=541-1.69FFCT-ND, TempCo="100 ppm/C", Tolerance_%=1%, Value2=0.25W, Value_Code=1R69, ValueDisplayed=1.69
R105: library part CMP-0022903-4, "RES, 205 k, 1%, 0.1 W, 0603", Manufacturer=Yageo, Power_W=100mW, Supplier Part Number 1=311-205KHRCT-ND, TempCo="100 ppm/C", Tolerance_%=1%, Value2=0.1W, Value_Code=205k
R106: library part CMP-0025736-4, "RES, 1.0 M, 5%, 0.1 W, AEC-Q200 Grade 0, 0603", Manufacturer=Vishay-Dale, Power_W=100mW, Supplier Part Number 1=541-1.0MGCT-ND, TempCo="200 ppm/C", Tolerance_%=5%, Value2=0.1W, Value_Code=1M00, ValueDisplayed=1.0M
R110: library part CMP-0022347-4, "RES, 34.8 k, 1%, 0.1 W, AEC-Q200 Grade 0, 0603", Manufacturer=Vishay-Dale, Power_W=100mW, Supplier Part Number 1=541-34.8KHCT-ND, TempCo="100 ppm/C", Tolerance_%=1%, Value2=0.1W, Value_Code=34k8, ValueDisplayed=34.8k
R111: library part CMP-0022126-4, "RES, 1.50 k, 1%, 0.1 W, AEC-Q200 Grade 0, 0603", Manufacturer=Vishay-Dale, Power_W=100mW, Supplier Part Number 1=541-1.50KHCT-ND, TempCo="100 ppm/C", Tolerance_%=1%, Value2=0.1W, Value_Code=1k50, ValueDisplayed=1.50k
R112: library part CMP-0022324-4, "RES, 30.1 k, 1%, 0.1 W, AEC-Q200 Grade 0, 0603", Manufacturer=Vishay-Dale, Power_W=100mW, Supplier Part Number 1=541-30.1KHCT-ND, TempCo="100 ppm/C", Tolerance_%=1%, Value2=0.1W, Value_Code=30k1, ValueDisplayed=30.1k
R113 R114 R204 R217: library part CMP-0025700-4, "RES, 100, 5%, 0.1 W, AEC-Q200 Grade 0, 0603", Manufacturer=Vishay-Dale, Power_W=100mW, Supplier Part Number 1=541-100GCT-ND, TempCo="200 ppm/C", Tolerance_%=5%, Value2=0.1W, Value_Code=100R, ValueDisplayed=100
R115 R116: library part CMP-0020803-2, "RES, 0, 5%, 0.125 W, 0805", Manufacturer="Yageo America", Power_W=125mW, Supplier Part Number 1=311-0.0ARCT-ND, TempCo="200 ppm/C", Tolerance_%=5%, Value2=0.125W, Value_Code=0000, ValueDisplayed=0
R117 R118 R119 R120: library part CMP-0015945-3, "RES, 33, 5%, 1 W, AEC-Q200 Grade 0, 2512", Manufacturer=Vishay-Dale, Power_W=1W, Supplier Part Number 1=541-33XCT-ND, TempCo="200 ppm/C", Tolerance_%=5%, Value_Code=33R0, ValueDisplayed=33
R121 R301: library part CMP-0122385-1, "10 kOhms ±1% 2W Chip Resistor 2512 (6432 Metric) Current Sense Thick Film", Digikey Part Number=118-CRM2512-FX-1002ELFCT-ND, Manufacturer=Bourns, Mouser Part Number=652-CRM2512FX1002ELF, Operating Temperature Range="-55°C to +155°C", Power_W=2W, TempCo=100ppm/°C, Tolerance_%=1%
R124: library part CMP-0022003-4, "RES, 10.0, 1%, 0.1 W, AEC-Q200 Grade 0, 0603", Manufacturer=Vishay-Dale, Power_W=100mW, Supplier Part Number 1=541-10.0HCT-ND, TempCo="100 ppm/C", Tolerance_%=1%, Value2=0.1W, Value_Code=10R0, ValueDisplayed=10.0
R125: library part CMP-0022012-4, "RES, 115 k, 1%, 0.1 W, AEC-Q200 Grade 0, 0603", Manufacturer=Vishay-Dale, Power_W=100mW, Supplier Part Number 1=541-115KHCT-ND, TempCo="100 ppm/C", Tolerance_%=1%, Value2=0.1W, Value_Code=115k
R207 R220: library part CMP-0022732-2, "RES, 2.00, 1%, 0.125 W, 0603", Manufacturer=Vishay/Beyschlag, Power_W=125mW, Supplier Part Number 1=MCT06030C2008FP500-ND, TempCo="50 ppm/C", Tolerance_%=1%, Value2=0.125W, Value_Code=2R00, ValueDisplayed=2.00
R208 R209 R210 R211 R221 R222 R223 R224 R231 R232 R233 R234: library part CMP-0022311-4, "RES, 2.49, 1%, 0.1 W, AEC-Q200 Grade 0, 0603", Manufacturer=Vishay-Dale, Power_W=100mW, Supplier Part Number 1=541-2.49HHCT-ND, TempCo="100 ppm/C", Tolerance_%=1%, Value2=0.1W, Value_Code=2R49, ValueDisplayed=2.49
SGND SGND_3: library part CMP-0055148-2, "Test Point, Multipurpose, Black, TH", Color=Black, Manufacturer="Keystone Electronics", PartNumber=5011, Supplier Part Number 1=36-5011-ND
